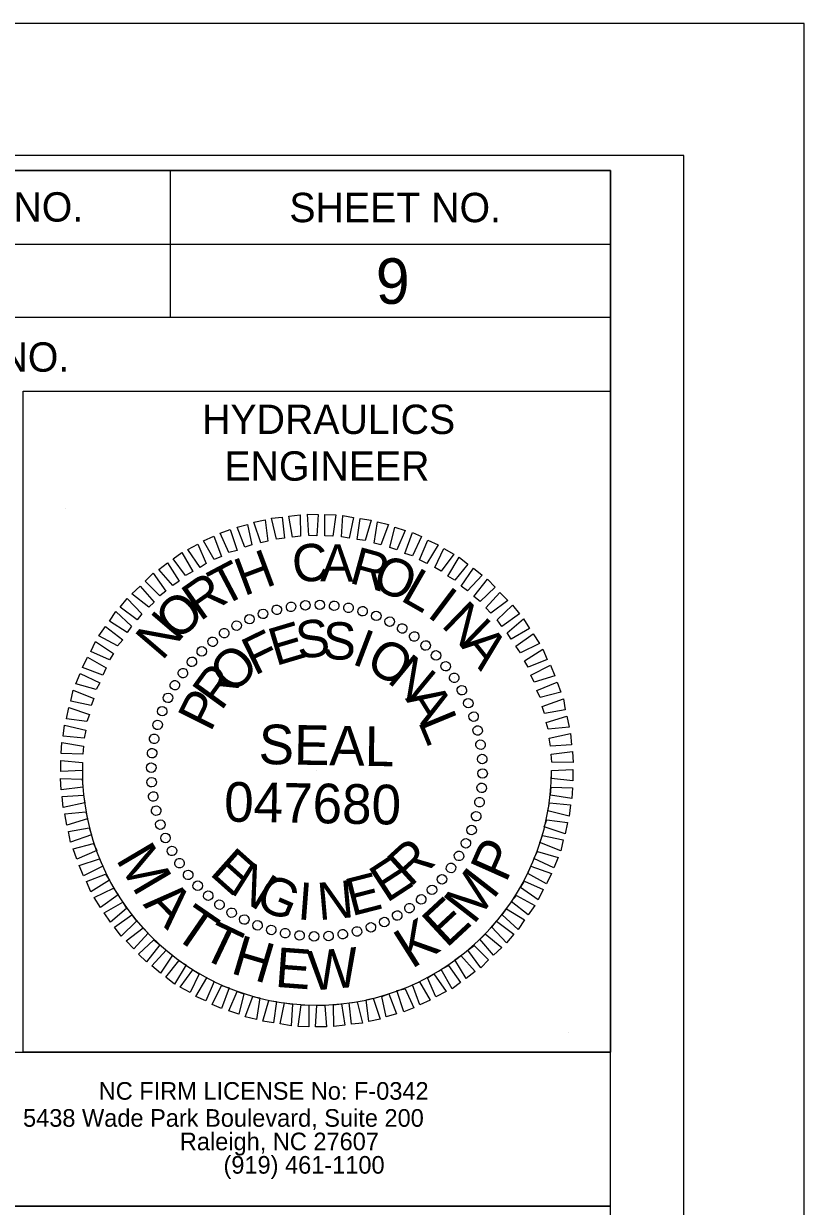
# Model space of a CAD drawing. Extents: x 2113883 to 2114903, y 714180 to 714840.
# Drawn here: x 2114822.8 to 2114902.6, y 714719.5 to 714840.3 of the extents above; entities that cross this region are included whole.
import ezdxf

# ---------------------------------------------------------------- set-up
doc = ezdxf.new("R2010")
doc.units = 0
for name, color, linetype in [('Old_Level_2', 7, 'Continuous'), ('Prop DSN Text', 7, 'Continuous'), ('Scratch_Level_0', 7, 'Continuous'), ('Sheet Block Title CELL', 7, 'Continuous'), ('Sheet Border Standard 30in CELL', 7, 'Continuous'), ('Sheet Cutting Line CELL', 7, 'Continuous'), ('Sheet Data Field CELL', 7, 'Continuous'), ('Sheet Plot Border Inside CELL', 7, 'Continuous'), ('Sheet Plot Border Outside CELL', 7, 'Continuous'), ('Sheet Profile CELL', 7, 'Continuous'), ('Sheet Sticker Exception Certification CELL', 7, 'Continuous')]:
    doc.layers.add(name, color=color, linetype=linetype)

msp = doc.modelspace()

# ---------------------------------------------------------------- linework, layer by layer
at = {"layer": 'Old_Level_2'}
for p, q in [((2114827.05, 714790.8), (2114827.05, 714790.8)), ((2114850.13, 714780.71), (2114850.13, 714780.71)), ((2114851.58, 714780.91), (2114851.58, 714780.91)), ((2114853.07, 714780.95), (2114853.07, 714780.95)), ((2114854.55, 714780.85), (2114854.55, 714780.85)), ((2114856, 714780.61), (2114856, 714780.61)), ((2114845.88, 714779.5), (2114845.88, 714779.5)), ((2114847.23, 714780.04), (2114847.23, 714780.04)), ((2114848.65, 714780.44), (2114848.65, 714780.44)), ((2114857.42, 714780.31), (2114857.42, 714780.31)), ((2114858.84, 714779.83), (2114858.84, 714779.83)), ((2114844.56, 714778.82), (2114844.56, 714778.82)), ((2114860.19, 714779.23), (2114860.19, 714779.23)), ((2114861.51, 714778.55), (2114861.51, 714778.55)), ((2114842.1, 714777.2), (2114842.1, 714777.2)), ((2114843.28, 714778.05), (2114843.28, 714778.05)), ((2114862.72, 714777.71), (2114862.72, 714777.71)), ((2114840.99, 714776.19), (2114840.99, 714776.19)), ((2114863.9, 714776.8), (2114863.9, 714776.8)), ((2114864.95, 714775.78), (2114864.95, 714775.78)), ((2114839.97, 714775.14), (2114839.97, 714775.14)), ((2114865.96, 714774.67), (2114865.96, 714774.67)), ((2114839.06, 714773.96), (2114839.06, 714773.96)), ((2114866.8, 714773.49), (2114866.8, 714773.49)), ((2114838.22, 714772.75), (2114838.22, 714772.75)), ((2114867.58, 714772.21), (2114867.58, 714772.21)), ((2114837.54, 714771.43), (2114837.54, 714771.43)), ((2114836.94, 714770.08), (2114836.94, 714770.08)), ((2114868.26, 714770.89), (2114868.26, 714770.89)), ((2114836.46, 714768.66), (2114836.46, 714768.66)), ((2114868.8, 714769.54), (2114868.8, 714769.54)), ((2114869.2, 714768.12), (2114869.2, 714768.12)), ((2114836.16, 714767.25), (2114836.16, 714767.25)), ((2114869.47, 714766.64), (2114869.47, 714766.64)), ((2114835.92, 714765.79), (2114835.92, 714765.79)), ((2114869.67, 714765.19), (2114869.67, 714765.19)), ((2114835.82, 714764.31), (2114835.82, 714764.31)), ((2114852.76, 714764.01), (2114852.76, 714764.01)), ((2114869.71, 714763.7), (2114869.71, 714763.7)), ((2114835.86, 714762.82), (2114835.86, 714762.82)), ((2114836.06, 714761.37), (2114836.06, 714761.37)), ((2114869.61, 714762.22), (2114869.61, 714762.22)), ((2114869.37, 714760.77), (2114869.37, 714760.77)), ((2114836.33, 714759.89), (2114836.33, 714759.89)), ((2114869.07, 714759.35), (2114869.07, 714759.35)), ((2114836.73, 714758.47), (2114836.73, 714758.47)), ((2114868.59, 714757.93), (2114868.59, 714757.93)), ((2114837.27, 714757.12), (2114837.27, 714757.12)), ((2114867.99, 714756.58), (2114867.99, 714756.58)), ((2114837.95, 714755.8), (2114837.95, 714755.8)), ((2114867.31, 714755.26), (2114867.31, 714755.26)), ((2114838.72, 714754.52), (2114838.72, 714754.52)), ((2114866.47, 714754.05), (2114866.47, 714754.05)), ((2114839.57, 714753.34), (2114839.57, 714753.34)), ((2114865.56, 714752.87), (2114865.56, 714752.87)), ((2114840.58, 714752.23), (2114840.58, 714752.23)), ((2114864.54, 714751.82), (2114864.54, 714751.82)), ((2114841.63, 714751.21), (2114841.63, 714751.21)), ((2114863.43, 714750.81), (2114863.43, 714750.81)), ((2114842.81, 714750.3), (2114842.81, 714750.3)), ((2114844.02, 714749.46), (2114844.02, 714749.46)), ((2114860.97, 714749.19), (2114860.97, 714749.19)), ((2114862.25, 714749.97), (2114862.25, 714749.97)), ((2114845.34, 714748.78), (2114845.34, 714748.78)), ((2114846.69, 714748.18), (2114846.69, 714748.18)), ((2114858.3, 714747.97), (2114858.3, 714747.97)), ((2114859.65, 714748.51), (2114859.65, 714748.51)), ((2114848.11, 714747.7), (2114848.11, 714747.7)), ((2114849.52, 714747.4), (2114849.52, 714747.4)), ((2114850.98, 714747.16), (2114850.98, 714747.16)), ((2114852.46, 714747.06), (2114852.46, 714747.06)), ((2114853.95, 714747.1), (2114853.95, 714747.1)), ((2114855.4, 714747.3), (2114855.4, 714747.3)), ((2114856.88, 714747.57), (2114856.88, 714747.57)), ((2114878.48, 714737.21), (2114878.48, 714737.21))]:
    msp.add_line(p, q, dxfattribs=at)
for points in [[(2114845.41, 714786.82), (2114844.63, 714788.85), (2114845.68, 714789.15), (2114846.12, 714787.06)], [(2114847.03, 714787.26), (2114846.32, 714789.39), (2114847.47, 714789.62), (2114847.74, 714787.43)], [(2114848.65, 714787.63), (2114848.11, 714789.79), (2114849.22, 714789.89), (2114849.46, 714787.73)], [(2114850.27, 714787.83), (2114849.9, 714789.99), (2114851.04, 714790.13), (2114851.08, 714787.93)], [(2114851.95, 714788), (2114851.79, 714790.2), (2114852.9, 714790.16), (2114852.76, 714787.97)], [(2114853.57, 714787.97), (2114853.57, 714790.16), (2114854.69, 714790.13), (2114854.38, 714787.93)], [(2114855.26, 714787.87), (2114855.4, 714790.06), (2114856.51, 714789.86), (2114856.07, 714787.73)], [(2114856.88, 714787.6), (2114857.19, 714789.76), (2114858.3, 714789.59), (2114857.69, 714787.5)], [(2114858.6, 714787.23), (2114858.94, 714789.42), (2114860.09, 714789.15), (2114859.31, 714787.06)], [(2114842.27, 714785.57), (2114841.19, 714787.46), (2114842.23, 714787.93), (2114843.01, 714785.88)], [(2114843.75, 714786.28), (2114842.88, 714788.24), (2114843.89, 714788.64), (2114844.6, 714786.48)], [(2114860.22, 714786.79), (2114860.73, 714788.88), (2114861.78, 714788.54), (2114860.93, 714786.55)], [(2114861.74, 714786.18), (2114862.52, 714788.31), (2114863.46, 714787.9), (2114862.52, 714785.94)], [(2114840.82, 714784.76), (2114839.57, 714786.58), (2114840.61, 714787.12), (2114841.46, 714785.17)], [(2114863.26, 714785.54), (2114864.1, 714787.53), (2114865.15, 714787.06), (2114864, 714785.17)], [(2114864.81, 714784.76), (2114865.72, 714786.69), (2114866.74, 714786.11), (2114865.45, 714784.36)], [(2114839.33, 714783.92), (2114838.08, 714785.64), (2114838.96, 714786.28), (2114840.07, 714784.32)], [(2114866.13, 714783.85), (2114867.31, 714785.81), (2114868.19, 714785.1), (2114866.87, 714783.45)], [(2114838.05, 714782.91), (2114836.6, 714784.53), (2114837.51, 714785.23), (2114838.69, 714783.34)], [(2114867.51, 714782.84), (2114868.76, 714784.69), (2114869.64, 714783.95), (2114868.15, 714782.37)], [(2114836.7, 714781.86), (2114835.21, 714783.34), (2114836.02, 714784.15), (2114837.34, 714782.33)], [(2114868.8, 714781.79), (2114870.18, 714783.55), (2114870.99, 714782.74), (2114869.44, 714781.29)], [(2114835.59, 714780.68), (2114833.86, 714782.06), (2114834.71, 714782.84), (2114836.13, 714781.22)], [(2114870.01, 714780.61), (2114871.46, 714782.2), (2114872.27, 714781.39), (2114870.52, 714780.07)], [(2114834.4, 714779.4), (2114832.65, 714780.71), (2114833.39, 714781.59), (2114834.88, 714780)], [(2114871.19, 714779.4), (2114872.74, 714780.91), (2114873.45, 714780), (2114871.66, 714778.72)], [(2114833.39, 714778.11), (2114831.57, 714779.26), (2114832.21, 714780.24), (2114833.83, 714778.75)], [(2114872.2, 714778.08), (2114873.86, 714779.5), (2114874.5, 714778.52), (2114872.61, 714777.44)], [(2114832.38, 714776.76), (2114830.49, 714777.78), (2114831.16, 714778.72), (2114832.92, 714777.37)], [(2114831.57, 714775.31), (2114829.65, 714776.16), (2114830.15, 714777.2), (2114831.97, 714775.95)], [(2114873.08, 714776.7), (2114874.87, 714777.98), (2114875.51, 714776.97), (2114873.55, 714776.02)], [(2114873.96, 714775.21), (2114875.85, 714776.39), (2114876.29, 714775.35), (2114874.36, 714774.57)], [(2114830.89, 714773.76), (2114828.8, 714774.54), (2114829.31, 714775.58), (2114831.23, 714774.5)], [(2114874.63, 714773.76), (2114876.63, 714774.77), (2114877.06, 714773.69), (2114874.97, 714773.02)], [(2114830.22, 714772.27), (2114828.13, 714772.88), (2114828.57, 714773.93), (2114830.59, 714772.98)], [(2114829.71, 714770.65), (2114827.62, 714771.09), (2114827.86, 714772.21), (2114829.98, 714771.36)], [(2114875.24, 714772.17), (2114877.3, 714773.05), (2114877.67, 714772), (2114875.58, 714771.46)], [(2114875.78, 714770.55), (2114877.94, 714771.33), (2114878.14, 714770.22), (2114876.02, 714769.84)], [(2114829.27, 714769.03), (2114827.18, 714769.3), (2114827.42, 714770.45), (2114829.54, 714769.74)], [(2114829, 714767.31), (2114826.84, 714767.52), (2114826.98, 714768.66), (2114829.17, 714768.12)], [(2114876.19, 714768.93), (2114878.31, 714769.57), (2114878.52, 714768.43), (2114876.39, 714768.22)], [(2114876.49, 714767.31), (2114878.68, 714767.79), (2114878.79, 714766.64), (2114876.63, 714766.5)], [(2114828.84, 714765.69), (2114826.64, 714765.76), (2114826.71, 714766.87), (2114828.9, 714766.5)], [(2114828.8, 714764.01), (2114826.61, 714763.9), (2114826.61, 714765.05), (2114828.8, 714764.82)], [(2114876.69, 714765.69), (2114878.89, 714765.96), (2114878.95, 714764.82), (2114876.76, 714764.88)], [(2114876.73, 714764.01), (2114878.92, 714764.11), (2114878.92, 714762.96), (2114876.73, 714763.2)], [(2114828.84, 714762.32), (2114826.64, 714762.05), (2114826.57, 714763.2), (2114828.77, 714763.13)], [(2114829.04, 714760.7), (2114826.84, 714760.23), (2114826.74, 714761.37), (2114828.9, 714761.51)], [(2114876.69, 714762.32), (2114878.89, 714762.25), (2114878.82, 714761.14), (2114876.63, 714761.51)], [(2114876.52, 714760.7), (2114878.68, 714760.5), (2114878.55, 714759.35), (2114876.36, 714759.89)], [(2114829.34, 714759.08), (2114827.22, 714758.44), (2114827.01, 714759.58), (2114829.14, 714759.79)], [(2114876.25, 714758.98), (2114878.35, 714758.71), (2114878.11, 714757.56), (2114875.98, 714758.27)], [(2114829.75, 714757.46), (2114827.59, 714756.68), (2114827.38, 714757.8), (2114829.51, 714758.17)], [(2114830.29, 714755.84), (2114828.23, 714754.96), (2114827.86, 714756.01), (2114829.95, 714756.55)], [(2114875.82, 714757.36), (2114877.91, 714756.92), (2114877.67, 714755.8), (2114875.55, 714756.65)], [(2114875.31, 714755.74), (2114877.4, 714755.13), (2114876.96, 714754.08), (2114874.94, 714755.03)], [(2114830.89, 714754.25), (2114828.9, 714753.24), (2114828.46, 714754.32), (2114830.56, 714754.99)], [(2114874.63, 714754.25), (2114876.73, 714753.48), (2114876.22, 714752.43), (2114874.3, 714753.51)], [(2114831.57, 714752.8), (2114829.68, 714751.62), (2114829.24, 714752.67), (2114831.16, 714753.44)], [(2114832.45, 714751.32), (2114830.66, 714750.03), (2114830.02, 714751.05), (2114831.97, 714751.99)], [(2114873.96, 714752.7), (2114875.88, 714751.86), (2114875.38, 714750.81), (2114873.55, 714752.06)], [(2114833.32, 714749.93), (2114831.67, 714748.51), (2114831.03, 714749.49), (2114832.92, 714750.57)], [(2114873.15, 714751.25), (2114875.04, 714750.24), (2114874.36, 714749.29), (2114872.61, 714750.64)], [(2114834.34, 714748.62), (2114832.78, 714747.1), (2114832.08, 714748.01), (2114833.86, 714749.29)], [(2114872.14, 714749.9), (2114873.96, 714748.75), (2114873.32, 714747.77), (2114871.7, 714749.26)], [(2114871.12, 714748.62), (2114872.88, 714747.3), (2114872.14, 714746.42), (2114870.65, 714748.01)], [(2114835.52, 714747.4), (2114834.07, 714745.81), (2114833.26, 714746.62), (2114835.01, 714747.94)], [(2114869.94, 714747.33), (2114871.66, 714745.95), (2114870.82, 714745.17), (2114869.4, 714746.79)], [(2114836.73, 714746.22), (2114835.35, 714744.46), (2114834.54, 714745.27), (2114836.09, 714746.73)], [(2114838.02, 714745.17), (2114836.77, 714743.32), (2114835.89, 714744.06), (2114837.37, 714745.65)], [(2114868.83, 714746.15), (2114870.31, 714744.67), (2114869.5, 714743.86), (2114868.19, 714745.68)], [(2114839.4, 714744.16), (2114838.22, 714742.2), (2114837.34, 714742.91), (2114838.66, 714744.57)], [(2114867.48, 714745.11), (2114868.93, 714743.49), (2114868.02, 714742.78), (2114866.84, 714744.67)], [(2114840.72, 714743.25), (2114839.8, 714741.33), (2114838.79, 714741.9), (2114840.07, 714743.65)], [(2114864.71, 714743.25), (2114865.96, 714741.43), (2114864.91, 714740.89), (2114864.07, 714742.84)], [(2114866.2, 714744.09), (2114867.45, 714742.37), (2114866.57, 714741.73), (2114865.45, 714743.69)], [(2114842.27, 714742.47), (2114841.42, 714740.48), (2114840.38, 714740.95), (2114841.53, 714742.84)], [(2114843.79, 714741.83), (2114843.01, 714739.71), (2114842.07, 714740.11), (2114843.01, 714742.07)], [(2114863.26, 714742.44), (2114864.34, 714740.55), (2114863.29, 714740.08), (2114862.52, 714742.14)], [(2114845.31, 714741.22), (2114844.8, 714739.13), (2114843.75, 714739.47), (2114844.6, 714741.46)], [(2114846.93, 714740.79), (2114846.59, 714738.59), (2114845.44, 714738.86), (2114846.22, 714740.95)], [(2114858.5, 714740.75), (2114859.21, 714738.63), (2114858.06, 714738.39), (2114857.79, 714740.58)], [(2114860.12, 714741.19), (2114860.9, 714739.17), (2114859.85, 714738.86), (2114859.41, 714740.95)], [(2114861.78, 714741.73), (2114862.65, 714739.77), (2114861.64, 714739.37), (2114860.93, 714741.53)], [(2114848.65, 714740.41), (2114848.34, 714738.25), (2114847.23, 714738.42), (2114847.84, 714740.52)], [(2114850.27, 714740.14), (2114850.13, 714737.95), (2114849.02, 714738.15), (2114849.46, 714740.28)], [(2114851.95, 714740.04), (2114851.95, 714737.85), (2114850.84, 714737.88), (2114851.14, 714740.08)], [(2114853.57, 714740.01), (2114853.74, 714737.82), (2114852.63, 714737.85), (2114852.76, 714740.04)], [(2114855.26, 714740.18), (2114855.63, 714738.02), (2114854.49, 714737.88), (2114854.45, 714740.08)], [(2114856.88, 714740.38), (2114857.42, 714738.22), (2114856.31, 714738.12), (2114856.07, 714740.28)]]:
    msp.add_lwpolyline(points, close=True, dxfattribs=at)
for centre, major_axis in [((2114847.25, 714780.01), (-0.158, 0.46)), ((2114848.67, 714780.43), (-0.118, 0.472)), ((2114850.12, 714780.73), (-0.076, 0.48)), ((2114851.58, 714780.89), (-0.034, 0.485)), ((2114853.06, 714780.93), (0.008, 0.486)), ((2114854.53, 714780.84), (0.051, 0.483)), ((2114855.99, 714780.62), (0.093, 0.477)), ((2114857.43, 714780.28), (0.134, 0.467)), ((2114844.56, 714778.81), (-0.236, 0.425)), ((2114845.88, 714779.47), (-0.198, 0.444)), ((2114858.83, 714779.81), (0.174, 0.454)), ((2114860.19, 714779.22), (0.213, 0.437)), ((2114843.3, 714778.04), (-0.272, 0.403)), ((2114861.48, 714778.52), (0.25, 0.417)), ((2114862.71, 714777.7), (0.286, 0.393)), ((2114842.11, 714777.16), (-0.306, 0.378)), ((2114863.87, 714776.78), (0.319, 0.367)), ((2114841, 714776.18), (-0.338, 0.35)), ((2114864.94, 714775.77), (0.35, 0.338)), ((2114839.99, 714775.11), (-0.367, 0.319)), ((2114865.92, 714774.66), (0.378, 0.306)), ((2114839.07, 714773.96), (-0.393, 0.286)), ((2114866.8, 714773.47), (0.403, 0.272)), ((2114838.25, 714772.72), (-0.417, 0.25)), ((2114867.57, 714772.21), (0.425, 0.236)), ((2114837.55, 714771.43), (-0.437, 0.213)), ((2114868.23, 714770.89), (0.444, 0.198)), ((2114836.96, 714770.07), (-0.454, 0.174)), ((2114868.77, 714769.52), (0.46, 0.158)), ((2114836.49, 714768.67), (-0.467, 0.134)), ((2114869.19, 714768.1), (0.472, 0.118)), ((2114836.15, 714767.24), (-0.477, 0.093)), ((2114835.93, 714765.78), (-0.483, 0.051)), ((2114869.48, 714766.65), (0.48, 0.076)), ((2114869.65, 714765.19), (0.485, 0.034)), ((2114835.84, 714764.3), (-0.486, 0.008)), ((2114869.69, 714763.71), (0.486, -0.008)), ((2114835.88, 714762.82), (-0.485, -0.034)), ((2114869.6, 714762.24), (0.483, -0.051)), ((2114836.04, 714761.36), (-0.48, -0.076)), ((2114869.38, 714760.78), (0.477, -0.093)), ((2114836.34, 714759.91), (-0.472, -0.118)), ((2114836.76, 714758.49), (-0.46, -0.158)), ((2114869.04, 714759.34), (0.467, -0.134)), ((2114837.3, 714757.12), (-0.444, -0.198)), ((2114868.57, 714757.94), (0.454, -0.174)), ((2114867.98, 714756.58), (0.437, -0.213)), ((2114837.96, 714755.8), (-0.425, -0.236)), ((2114867.28, 714755.29), (0.417, -0.25)), ((2114838.73, 714754.54), (-0.403, -0.272)), ((2114866.46, 714754.06), (0.393, -0.286)), ((2114839.61, 714753.35), (-0.378, -0.306)), ((2114840.59, 714752.25), (-0.35, -0.338)), ((2114865.54, 714752.9), (0.367, -0.319)), ((2114841.66, 714751.23), (-0.319, -0.367)), ((2114864.52, 714751.83), (0.338, -0.35)), ((2114842.81, 714750.31), (-0.286, -0.393)), ((2114862.23, 714749.97), (0.272, -0.403)), ((2114863.42, 714750.85), (0.306, -0.378)), ((2114844.05, 714749.49), (-0.25, -0.417)), ((2114845.34, 714748.79), (-0.213, -0.437)), ((2114860.97, 714749.2), (0.236, -0.425)), ((2114846.7, 714748.2), (-0.174, -0.454)), ((2114848.1, 714747.73), (-0.134, -0.467)), ((2114856.86, 714747.58), (0.118, -0.472)), ((2114858.28, 714748), (0.158, -0.46)), ((2114859.65, 714748.54), (0.198, -0.444)), ((2114849.53, 714747.39), (-0.093, -0.477)), ((2114850.99, 714747.17), (-0.051, -0.483)), ((2114852.47, 714747.08), (-0.008, -0.486)), ((2114853.95, 714747.12), (0.034, -0.485)), ((2114855.41, 714747.29), (0.076, -0.48))]:
    msp.add_ellipse(centre, major_axis=major_axis, ratio=0.999708, dxfattribs=at)
at = {"layer": 'Scratch_Level_0'}
msp.add_arc((2114852.76, 714764.01), 23.96, 180, 360, dxfattribs=at)
at = {"layer": 'Sheet Block Title CELL'}
msp.add_lwpolyline([(2114762.73, 714735.26), (2114882.73, 714735.26), (2114882.73, 714719.51), (2114762.73, 714719.51)], close=True, dxfattribs=at)
at = {"layer": 'Sheet Border Standard 30in CELL'}
msp.add_line((2114882.76, 714810.26), (2114882.76, 714802.76), dxfattribs=at)
msp.add_lwpolyline([(2114822.76, 714802.76), (2114882.76, 714802.76), (2114882.76, 714735.26), (2114822.76, 714735.26)], close=True, dxfattribs=at)
at = {"layer": 'Sheet Cutting Line CELL'}
for p, q in [((2114902.56, 714840.29), (2113882.56, 714840.29)), ((2114902.56, 714180.29), (2114902.56, 714840.29))]:
    msp.add_line(p, q, dxfattribs=at)
at = {"layer": 'Sheet Plot Border Inside CELL'}
msp.add_lwpolyline([(2113890.36, 714193.76), (2114890.26, 714193.76), (2114890.26, 714826.82), (2113890.36, 714826.82)], close=True, dxfattribs=at)
at = {"layer": 'Sheet Plot Border Outside CELL'}
msp.add_lwpolyline([(2113882.56, 714180.29), (2114902.56, 714180.29), (2114902.56, 714840.29), (2113882.56, 714840.29)], close=True, dxfattribs=at)
at = {"layer": 'Sheet Profile CELL'}
for p, q in [((2114837.76, 714825.26), (2114837.76, 714810.26)), ((2114762.73, 714817.76), (2114882.76, 714817.76))]:
    msp.add_line(p, q, dxfattribs=at)
for points in [[(2114882.76, 714825.29), (2113982.76, 714825.29), (2113982.76, 714195.29), (2114882.76, 714195.29)], [(2114762.73, 714825.29), (2114882.76, 714825.29), (2114882.76, 714810.26), (2114762.73, 714810.26)]]:
    msp.add_lwpolyline(points, close=True, dxfattribs=at)
at = {"layer": 'Sheet Sticker Exception Certification CELL'}
msp.add_line((2114762.73, 714719.51), (2114882.76, 714719.51), dxfattribs=at)

# ---------------------------------------------------------------- texts
at = {"layer": 'Old_Level_2'}
for s, height, rotation, p in [('C', 3.81, 6.2199, (2114850.44, 714783.14)), ('A', 3.81, 359.0203, (2114853.1, 714783.34)), ('R', 3.83, 344.6211, (2114855.94, 714783.21)), ('T', 3.88, 27.8198, (2114843.11, 714780.68)), ('H', 3.85, 20.6195, (2114845.31, 714781.79)), ('O', 3.86, 337.4212, (2114858.2, 714782.7)), ('L', 3.89, 330.2209, (2114861.17, 714781.45)), ('R', 3.91, 35.0205, (2114840.82, 714779.19)), ('O', 3.93, 42.2217, (2114838.49, 714777.1)), ('I', 3.92, 323.0201, (2114863.9, 714779.83)), ('N', 3.93, 315.8189, (2114865.35, 714778.79)), ('N', 3.93, 49.4235, (2114836.94, 714775.14)), ('S', 3.81, 7.2556, (2114850.87, 714775.38)), ('F', 3.88, 25.967, (2114846.39, 714773.66)), ('E', 3.84, 16.6111, (2114848.55, 714774.67)), ('S', 3.81, 357.9004, (2114853.3, 714775.41)), ('I', 3.86, 339.1896, (2114856.21, 714774.94)), ('O', 3.89, 329.8335, (2114857.56, 714774.47)), ('A', 3.93, 308.6172, (2114867.34, 714776.8)), ('O', 3.93, 44.6812, (2114844.16, 714771.67)), ('N', 3.92, 320.4766, (2114859.82, 714773.12)), ('R', 3.93, 54.0397, (2114842.98, 714770.01)), ('P', 3.9, 63.3989, (2114841.9, 714767.85)), ('A', 3.92, 301.7603, (2114861.74, 714771.36)), ('L', 3.88, 292.4009, (2114863.06, 714769.03)), ('SEAL', 4.049, 359, (2114846.79, 714764.68)), ('047680', 4.05, 359, (2114843.26, 714758.8)), ('M', 4.16, 300.5946, (2114832.16, 714754.95)), ('R', 3.93, 42.4814, (2114862.28, 714752.02)), ('P', 4.13, 65.9822, (2114872.08, 714752.45)), ('E', 3.93, 318.2769, (2114841.69, 714753.44)), ('E', 3.9, 33.1241, (2114859.89, 714750.44)), ('N', 3.9, 327.634, (2114843.72, 714751.62)), ('M', 4.18, 52.1673, (2114868.76, 714748.17)), ('G', 3.86, 336.9902, (2114846.28, 714750.1)), ('N', 3.81, 5.0564, (2114852.97, 714748.72)), ('E', 3.83, 14.4118, (2114856.31, 714749.12)), ('A', 4.18, 314.4095, (2114834.92, 714750.29)), ('I', 3.81, 355.7012, (2114850.71, 714748.82)), ('T', 4.16, 325.4865, (2114837.89, 714747.12)), ('E', 4.18, 42.8526, (2114865.99, 714745.79)), ('T', 4.12, 334.4865, (2114840.71, 714745)), ('K', 4.15, 32.342, (2114862.44, 714743.69)), ('H', 4.08, 343.4865, (2114843.83, 714743.35)), ('E', 4.05, 355.7279, (2114848.41, 714741.93)), ('W', 4.05, 5.0426, (2114852.05, 714741.51))]:
    msp.add_text(s, height=height, rotation=rotation, dxfattribs=at).set_placement(p)
at = {"layer": 'Prop DSN Text'}
for s, p in [('NC FIRM LICENSE No: F-0342', (2114830.47, 714730.39)), ('5438 Wade Park Boulevard, Suite 200', (2114822.74, 714727.63)), ('Raleigh, NC 27607', (2114838.76, 714725.23)), ('(919) 461-1100', (2114843.22, 714722.84))]:
    msp.add_text(s, height=1.8, rotation=0, dxfattribs=at).set_placement(p)
at = {"layer": 'Sheet Border Standard 30in CELL'}
for s, height, p in [('R/W SHEET NO.', 3.0001, (2114796.93, 714804.74)), ('HYDRAULICS', 3, (2114841.03, 714798.38)), ('ENGINEER', 3, (2114843.31, 714793.61))]:
    msp.add_text(s, height=height, rotation=0, dxfattribs=at).set_placement(p)
at = {"layer": 'Sheet Data Field CELL'}
msp.add_text('9', height=4.65, dxfattribs=at).set_placement((2114858.78, 714811.67))
at = {"layer": 'Sheet Profile CELL'}
for s, height, p in [('PROJECT REFERENCE NO.', 3.0001, (2114776.06, 714820.07)), ('SHEET NO.', 3, (2114849.95, 714820.01))]:
    msp.add_text(s, height=height, dxfattribs=at).set_placement(p)

doc.saveas('drawing.dxf')
